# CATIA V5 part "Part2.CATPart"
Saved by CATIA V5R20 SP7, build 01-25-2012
Part number: squelette axe
Publications: "rayonpart2"
Bounding box of the stored display mesh (mm): x -9.69 to 10.31, y -60 to -60, z 10 to 30
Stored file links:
  F:\Travaux\Modélisations\CFAO_2011\CFAO_2011_MMS\CFAO_2011_MMS_DONE\CFAO_2011_MMS_jboiteux\Catia\Part2.CATPart
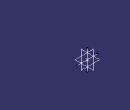
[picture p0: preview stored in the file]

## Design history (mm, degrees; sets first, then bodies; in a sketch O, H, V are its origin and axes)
Parameters
  rayonpart2 = 7.5 mm
Body1 (main body)
  Point1: stored without definition
  Line1 to Line3: stored without definition
  Point2: type OnCurve, Support Line3, Length 18 {= rayonpart2 *12/5}
  Line4: type Normal, RefPoint Point2, RefSkin yz-plane, Start -10, End 10
  Line5: type Normal, RefPoint Point2, RefSkin xy-plane, Start -10, End 10
  Plane1: stored without definition
  Plane2: type OffsetPt, RefPlane yz-plane, RefPoint Point2
  Plane3: type 2Lines, Element1 Line4, Element2 Line5
  Plane4: type OffsetPt, RefPlane xy-plane, RefPoint Point2
  Point3: stored without definition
